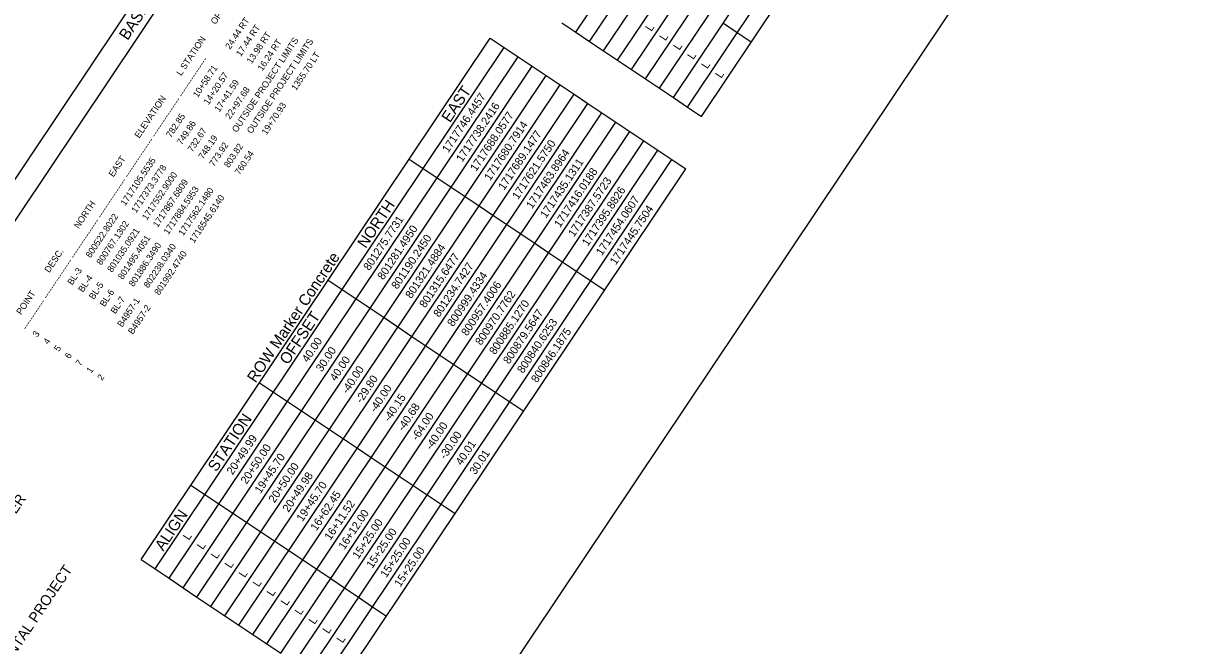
# Model space of a CAD drawing. Extents: x 1716977 to 1718461, y 800056 to 801805.
# Drawn here: x 1717724 to 1718461, y 800641 to 801029 of the extents above; entities that cross this region are included whole.
import ezdxf

# ---------------------------------------------------------------- set-up
doc = ezdxf.new("R2010")
doc.units = 0
for name, color, linetype in [('CTL Sheet Border CELL', 7, 'Continuous'), ('CTL Sheet Notes CELL', 7, 'Continuous'), ('CTL Sheet Table Cell', 7, 'Continuous'), ('CTL Sheet Text', 7, 'Continuous'), ('Old_Level_2', 7, 'Continuous')]:
    doc.layers.add(name, color=color, linetype=linetype)

msp = doc.modelspace()

# ---------------------------------------------------------------- linework, layer by layer
at = {"layer": 'CTL Sheet Border CELL'}
for points in [[(1717702.35, 801780.65), (1716976.84, 800696.7), (1717735.6, 800188.84), (1718461.11, 801272.8)], [(1717691.02, 800890.37), (1717913.14, 801222.23), (1717925.03, 801214.27), (1717702.93, 800882.43)]]:
    msp.add_lwpolyline(points, close=True, dxfattribs=at)
at = {"layer": 'CTL Sheet Table Cell'}
for p, q in [((1718069.05, 801023.63), (1718287.09, 801349.39)), ((1718077.78, 801017.79), (1718295.82, 801343.55)), ((1718086.5, 801011.94), (1718304.54, 801337.71)), ((1718095.23, 801006.1), (1718313.27, 801331.87)), ((1718103.95, 801000.26), (1718321.99, 801326.03)), ((1718112.68, 800994.42), (1718330.72, 801320.19)), ((1718121.41, 800988.58), (1718339.45, 801314.35)), ((1718130.13, 800982.74), (1718348.17, 801308.51)), ((1718138.86, 800976.9), (1718356.9, 801302.67)), ((1718147.58, 800971.06), (1718365.62, 801296.83)), ((1718060.33, 801029.47), (1718069.05, 801023.63)), ((1718161.28, 801029.28), (1718170.01, 801023.44)), ((1717797.62, 800694.18), (1718015.66, 801019.94)), ((1718015.66, 801019.94), (1718024.39, 801014.1)), ((1718069.05, 801023.63), (1718077.78, 801017.79)), ((1718077.78, 801017.79), (1718086.5, 801011.94)), ((1718170.01, 801023.44), (1718178.73, 801017.6)), ((1717806.35, 800688.34), (1718024.39, 801014.1)), ((1718024.39, 801014.1), (1718033.11, 801008.26)), ((1718086.5, 801011.94), (1718095.23, 801006.1)), ((1717815.07, 800682.5), (1718033.11, 801008.26)), ((1717823.8, 800676.66), (1718041.84, 801002.42)), ((1718033.11, 801008.26), (1718041.84, 801002.42)), ((1718041.84, 801002.42), (1718050.56, 800996.58)), ((1718095.23, 801006.1), (1718103.95, 801000.26)), ((1717832.52, 800670.82), (1718050.56, 800996.58)), ((1718050.56, 800996.58), (1718059.29, 800990.74)), ((1718103.95, 801000.26), (1718112.68, 800994.42)), ((1717841.25, 800664.97), (1718059.29, 800990.74)), ((1718059.29, 800990.74), (1718068.02, 800984.9)), ((1718112.68, 800994.42), (1718121.41, 800988.58)), ((1718121.41, 800988.58), (1718130.13, 800982.74)), ((1717849.98, 800659.13), (1718068.02, 800984.9)), ((1718068.02, 800984.9), (1718076.74, 800979.06)), ((1718130.13, 800982.74), (1718138.86, 800976.9)), ((1717858.7, 800653.29), (1718076.74, 800979.06)), ((1717867.43, 800647.45), (1718085.47, 800973.22)), ((1718076.74, 800979.06), (1718085.47, 800973.22)), ((1718085.47, 800973.22), (1718094.19, 800967.38)), ((1718138.86, 800976.9), (1718147.58, 800971.06)), ((1717876.15, 800641.61), (1718094.19, 800967.38)), ((1718094.19, 800967.38), (1718102.92, 800961.54)), ((1717884.88, 800635.77), (1718102.92, 800961.54)), ((1718102.92, 800961.54), (1718111.64, 800955.7)), ((1717893.61, 800629.93), (1718111.64, 800955.7)), ((1718111.64, 800955.7), (1718120.37, 800949.86)), ((1717902.33, 800624.09), (1718120.37, 800949.86)), ((1717911.06, 800618.25), (1718129.1, 800944.02)), ((1717965.04, 800944.32), (1717973.77, 800938.48)), ((1718120.37, 800949.86), (1718129.1, 800944.02)), ((1718129.1, 800944.02), (1718137.82, 800938.18)), ((1717919.78, 800612.41), (1718137.82, 800938.18)), ((1717973.77, 800938.48), (1717982.5, 800932.64)), ((1717982.5, 800932.64), (1717991.22, 800926.8)), ((1717991.22, 800926.8), (1717999.95, 800920.96)), ((1717999.95, 800920.96), (1718008.67, 800915.12)), ((1718008.67, 800915.12), (1718017.4, 800909.28)), ((1718017.4, 800909.28), (1718026.13, 800903.44)), ((1718026.13, 800903.44), (1718034.85, 800897.59)), ((1718034.85, 800897.59), (1718043.58, 800891.75)), ((1718043.58, 800891.75), (1718052.3, 800885.91)), ((1718052.3, 800885.91), (1718061.03, 800880.07)), ((1718061.03, 800880.07), (1718069.75, 800874.23)), ((1718069.75, 800874.23), (1718078.48, 800868.39)), ((1717914.43, 800868.69), (1717923.15, 800862.85)), ((1717923.15, 800862.85), (1717931.88, 800857.01)), ((1718078.48, 800868.39), (1718087.21, 800862.55)), ((1717931.88, 800857.01), (1717940.61, 800851.17)), ((1717940.61, 800851.17), (1717949.33, 800845.33)), ((1717949.33, 800845.33), (1717958.06, 800839.49)), ((1717958.06, 800839.49), (1717966.78, 800833.65)), ((1717966.78, 800833.65), (1717975.51, 800827.81)), ((1717975.51, 800827.81), (1717984.23, 800821.97)), ((1717984.23, 800821.97), (1717992.96, 800816.13)), ((1717992.96, 800816.13), (1718001.69, 800810.29)), ((1717871.6, 800804.7), (1717880.32, 800798.86)), ((1718001.69, 800810.29), (1718010.41, 800804.45)), ((1718010.41, 800804.45), (1718019.14, 800798.61)), ((1717880.32, 800798.86), (1717889.05, 800793.02)), ((1718019.14, 800798.61), (1718027.86, 800792.77)), ((1717889.05, 800793.02), (1717897.78, 800787.18)), ((1718027.86, 800792.77), (1718036.59, 800786.93)), ((1717897.78, 800787.18), (1717906.5, 800781.34)), ((1717906.5, 800781.34), (1717915.23, 800775.5)), ((1717915.23, 800775.5), (1717923.95, 800769.66)), ((1717923.95, 800769.66), (1717932.68, 800763.82)), ((1717932.68, 800763.82), (1717941.41, 800757.98)), ((1717941.41, 800757.98), (1717950.13, 800752.14)), ((1717950.13, 800752.14), (1717958.86, 800746.3)), ((1717958.86, 800746.3), (1717967.58, 800740.46)), ((1717828.77, 800740.71), (1717837.5, 800734.87)), ((1717967.58, 800740.46), (1717976.31, 800734.62)), ((1717837.5, 800734.87), (1717846.22, 800729.03)), ((1717976.31, 800734.62), (1717985.03, 800728.78)), ((1717846.22, 800729.03), (1717854.95, 800723.19)), ((1717854.95, 800723.19), (1717863.67, 800717.35)), ((1717985.03, 800728.78), (1717993.76, 800722.94)), ((1717863.67, 800717.35), (1717872.4, 800711.51)), ((1717872.4, 800711.51), (1717881.12, 800705.67)), ((1717881.12, 800705.67), (1717889.85, 800699.83)), ((1717797.62, 800694.18), (1717806.35, 800688.34)), ((1717889.85, 800699.83), (1717898.58, 800693.99)), ((1717898.58, 800693.99), (1717907.3, 800688.15)), ((1717806.35, 800688.34), (1717815.07, 800682.5)), ((1717907.3, 800688.15), (1717916.03, 800682.31)), ((1717815.07, 800682.5), (1717823.8, 800676.66)), ((1717916.03, 800682.31), (1717924.75, 800676.47)), ((1717823.8, 800676.66), (1717832.52, 800670.82)), ((1717832.52, 800670.82), (1717841.25, 800664.97)), ((1717924.75, 800676.47), (1717933.48, 800670.63)), ((1717841.25, 800664.97), (1717849.98, 800659.13)), ((1717933.48, 800670.63), (1717942.21, 800664.79)), ((1717942.21, 800664.79), (1717950.93, 800658.95)), ((1717849.98, 800659.13), (1717858.7, 800653.29)), ((1717858.7, 800653.29), (1717867.43, 800647.45)), ((1717867.43, 800647.45), (1717876.15, 800641.61)), ((1717876.15, 800641.61), (1717884.88, 800635.77))]:
    msp.add_line(p, q, dxfattribs=at)

# ---------------------------------------------------------------- texts
at = {"layer": 'CTL Sheet Notes CELL'}
for s, p in [('EAST', (1717990.54, 800966.68)), ('NORTH', (1717937.99, 800888.17)), ('ROW Marker Concrete', (1717869.13, 800804.17)), ('OFFSET', (1717889.34, 800815.48)), ('STATION', (1717844.58, 800748.6)), ('ALIGN', (1717811.45, 800699.11))]:
    msp.add_text(s, height=7, rotation=56.20506, dxfattribs=at).set_placement(p)
at = {"layer": 'CTL Sheet Text'}
for s, height, p in [('BASELINE DATA', 7.0434, (1717789.18, 801018.13)), ('    POINT          DESC.           NORTH             EAST          ELEVATION           L STATION       OFFSET', 4.05, (1717719.37, 800841.8)), ('3                        BL-3      800522.8022     1717105.5535           782.85         10+58.71         24.44 RT', 4.05, (1717732.83, 800832.79)), ('4                        BL-4      800767.1302     1717373.3778           749.86         14+20.57         17.44 RT', 4.05, (1717739.56, 800828.29)), ('L', 5, (1718116.32, 801023.69)), ('5                        BL-5      801035.0921     1717552.9000           732.67         17+41.59         13.98 RT', 4.05, (1717746.29, 800823.78)), ('6                        BL-6      801495.4051     1717867.6809           748.19         22+97.68         16.24 RT', 4.05, (1717753.02, 800819.27)), ('7                        BL-7      801886.3490     1717884.5953           773.92      OUTSIDE PROJECT LIMITS                 ', 4.05, (1717759.75, 800814.77)), ('1                     B4957-1      802238.0340     1717562.1480           803.82      OUTSIDE PROJECT LIMITS                 ', 4.05, (1717766.49, 800810.26)), ('L', 5, (1718125.05, 801017.85)), ('2                     B4957-2      801992.4740     1716545.6140           760.54         19+70.93       1355.70 LT', 4.05, (1717773.22, 800805.76)), ('L', 5, (1718133.78, 801012.01)), ('L', 5, (1718142.5, 801006.17)), ('------------ ---------------- ---------------- ---------------- ---------------- ---------------- ----------------', 4.05, (1717726.1, 800837.3)), ('L', 5, (1718151.23, 801000.33)), ('L', 5, (1718159.95, 800994.49)), ('1717746.4457', 5, (1717989.42, 800947.93)), ('1717738.2416', 5, (1717998.15, 800942.09)), ('1717688.0577', 5, (1718006.87, 800936.25)), ('1717680.7914', 5, (1718015.6, 800930.41)), ('1717689.1477', 5, (1718024.33, 800924.57)), ('1717621.5750', 5, (1718033.05, 800918.73)), ('1717463.8964', 5, (1718041.78, 800912.89)), ('1717435.1311', 5, (1718050.5, 800907.05)), ('1717416.0188', 5, (1718059.23, 800901.21)), ('1717387.5723', 5, (1718067.96, 800895.37)), ('1717395.8826', 5, (1718076.68, 800889.53)), ('1717454.0607', 5, (1718085.41, 800883.69)), ('1717445.7504', 5, (1718094.13, 800877.85)), ('801275.7731', 5, (1717940.19, 800874.37)), ('801281.4950', 5, (1717948.91, 800868.53)), ('801190.2450', 5, (1717957.64, 800862.69)), ('801321.4884', 5, (1717966.36, 800856.85)), ('801315.6477', 5, (1717975.09, 800851.01)), ('801234.7427', 5, (1717983.82, 800845.17)), ('800999.4334', 5, (1717992.54, 800839.33)), ('800957.4006', 5, (1718001.27, 800833.49)), ('800970.7762', 5, (1718009.99, 800827.65)), ('800885.1270', 5, (1718018.72, 800821.81)), ('800879.5647', 5, (1718027.45, 800815.96)), ('800840.6253', 5, (1718036.17, 800810.12)), ('800846.1875', 5, (1718044.9, 800804.28)), ('40.00', 5, (1717901.74, 800816.93)), ('30.00', 5, (1717910.47, 800811.09)), ('40.00', 5, (1717919.19, 800805.25)), ('-40.00', 5, (1717926.54, 800797.35)), ('-29.80', 5, (1717935.27, 800791.51)), ('-40.00', 5, (1717943.99, 800785.67)), ('-40.15', 5, (1717952.72, 800779.83)), ('-40.68', 5, (1717961.44, 800773.99)), ('-64.00', 5, (1717970.17, 800768.14)), ('-40.00', 5, (1717978.89, 800762.3)), ('-30.00', 5, (1717987.62, 800756.46)), ('20+49.99', 5, (1717854.77, 800746.76)), ('40.01', 5, (1717997.73, 800752.69)), ('20+50.00', 5, (1717863.5, 800740.92)), ('19+45.70', 5, (1717872.23, 800735.07)), ('30.01', 5, (1718006.45, 800746.84)), ('20+50.00', 5, (1717880.95, 800729.23)), ('20+49.98', 5, (1717889.68, 800723.39)), ('19+45.70', 5, (1717898.4, 800717.55)), ('16+62.45', 5, (1717907.13, 800711.71)), ('16+11.52', 5, (1717915.85, 800705.87)), ('16+12.00', 5, (1717924.58, 800700.03)), ('15+25.00', 5, (1717933.31, 800694.19)), ('L', 5, (1717827.44, 800705.92)), ('15+25.00', 5, (1717942.03, 800688.35)), ('15+25.00', 5, (1717950.76, 800682.51)), ('L', 5, (1717836.17, 800700.08)), ('15+25.00', 5, (1717959.48, 800676.67)), ('L', 5, (1717844.89, 800694.24)), ('L', 5, (1717853.62, 800688.4)), ('L', 5, (1717862.35, 800682.56)), ('L', 5, (1717871.07, 800676.72)), ('L', 5, (1717879.8, 800670.88)), ('L', 5, (1717888.52, 800665.04)), ('L', 5, (1717897.25, 800659.2)), ('L', 5, (1717905.97, 800653.36)), ('L', 5, (1717914.7, 800647.52)), ('L', 5, (1717923.43, 800641.68))]:
    msp.add_text(s, height=height, rotation=56.20506, dxfattribs=at).set_placement(p)
at = {"layer": 'Old_Level_2'}
for s, rotation, p in [('SITE CALIBRATION INFORMATION HAS NOT BEEN PROVIDED FOR THIS PROJECT. IF FURTHER', 56.20506, (1717502.7, 800398.52)), ('INDICATES GEODETIC CONTROL MONUMENTS USED OR SET FOR HORIZONTAL PROJECT', 56.09981, (1717541.2, 800369.85))]:
    msp.add_text(s, height=6.5218, rotation=rotation, dxfattribs=at).set_placement(p)

doc.saveas('drawing.dxf')
